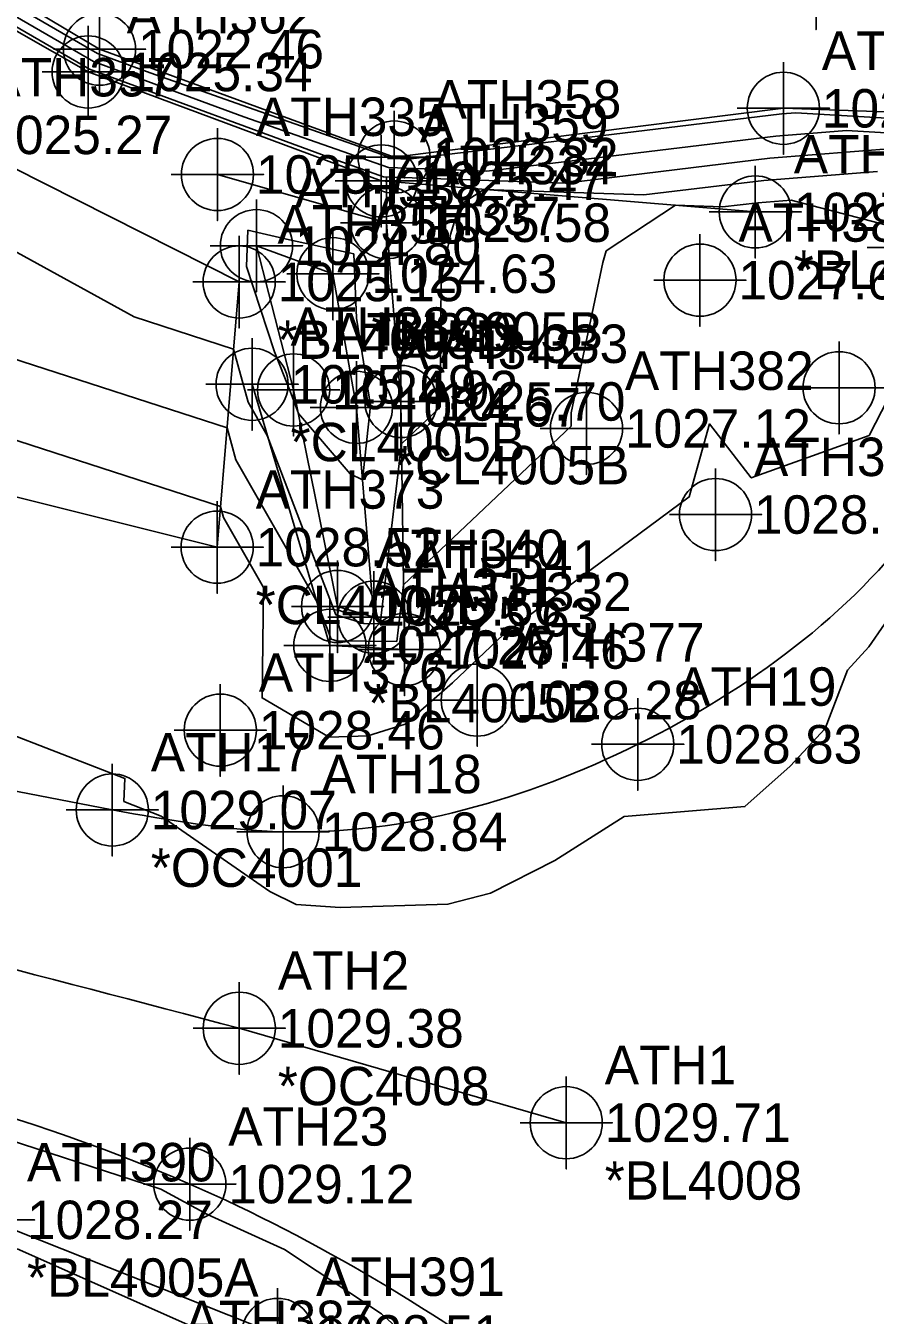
# Model space of a CAD drawing. Extents: x 1213164 to 1213550, y 766120 to 766870.
# Drawn here: x 1213249.2 to 1213304.4, y 766399.6 to 766483.4 of the extents above; entities that cross this region are included whole.
import ezdxf

# ---------------------------------------------------------------- set-up
doc = ezdxf.new("R2010")
doc.units = 0
for name, color, linetype in [('Default', 7, 'Continuous'), ('Exist DTM Breakline', 7, 'Continuous'), ('Exist DTM Breakline Cogo Comment', 7, 'Continuous'), ('Exist DTM Breakline Cogo Elevation', 7, 'Continuous'), ('Exist DTM Breakline Cogo Number', 7, 'Continuous'), ('Exist DTM Breakline Cogo Point CELL', 7, 'Continuous'), ('Exist DTM Crownline', 7, 'Continuous'), ('Exist DTM Crownline Cogo Point CELL', 7, 'Continuous'), ('Exist DTM Drainline Cogo Elevation', 7, 'Continuous'), ('Exist DTM Drainline Cogo Number', 7, 'Continuous'), ('Exist DTM Drainline Cogo Point CELL', 7, 'Continuous'), ('Exist DTM Regular Point CELL', 7, 'Continuous'), ('Exist DTM Regular Point Cogo Comment', 7, 'Continuous'), ('Exist DTM Regular Point Cogo Elevation', 7, 'Continuous'), ('Exist DTM Regular Point Cogo Number', 7, 'Continuous'), ('Exist DTM Regular Point Underwater CELL', 7, 'Continuous'), ('Exist DTM Regular Point Underwater Cogo Comment', 7, 'Continuous'), ('Exist DTM Regular Point Underwater Cogo Elevation', 7, 'Continuous'), ('Exist DTM Regular Point Underwater Cogo Number', 7, 'Continuous'), ('Exist Hydro Stream or Body of Water', 7, 'Continuous'), ('Exist Roads EOP', 7, 'Continuous'), ('Exist Roads EOP Cogo Point CELL', 7, 'Continuous')]:
    doc.layers.add(name, color=color, linetype=linetype)

msp = doc.modelspace()

# ---------------------------------------------------------------- linework, layer by layer
at = {"layer": 'Default'}
for points in [[(1213232.0588285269, 766494.9257890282), (1213249.4618614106, 766484.155977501), (1213253.8233532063, 766481.6289549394), (1213257.2612087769, 766480.3647865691), (1213273.0448975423, 766474.7949686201), (1213274.015282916, 766474.7610461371), (1213298.2993294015, 766477.708404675), (1213299.2070299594, 766477.7805484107), (1213310.3054437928, 766477.1165972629)], [(1213232.8561839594, 766492.4547874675), (1213253.311741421, 766480.6029584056), (1213269.4354109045, 766474.6739621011), (1213272.4180544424, 766473.6214336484), (1213284.2307344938, 766473.2084890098), (1213297.5165715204, 766474.8209931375), (1213305.7740741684, 766475.4772966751)], [(1213241.159022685, 766488.3053824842), (1213253.5675473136, 766481.1159566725), (1213263.3483098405, 766477.5193743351), (1213272.7314759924, 766474.2082011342), (1213279.123008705, 766473.9847675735), (1213297.907950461, 766476.2646989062), (1213302.490552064, 766476.6289225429), (1213309.1317715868, 766476.2316184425)], [(1213241.8495821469, 766472.4040495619), (1213256.20619088, 766464.510006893), (1213262.6712030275, 766462.4170151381), (1213263.6274647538, 766458.9801034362), (1213264.86498659, 766456.8053627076), (1213269.324798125, 766445.152285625), (1213271.1324427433, 766444.5771108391), (1213272.1914347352, 766444.5668498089), (1213273.5869493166, 766456.2710233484), (1213276.0928715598, 766458.6461009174), (1213276.1688284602, 766466.9726738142), (1213276.7759325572, 766469.8664609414), (1213277.3577727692, 766471.7631941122), (1213278.9261876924, 766472.7962), (1213289.338460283, 766472.4322104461), (1213297.1251925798, 766473.3772873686), (1213304.5200093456, 766473.965024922)], [(1213248.2040699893, 766461.848819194), (1213262.2482288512, 766457.3021442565), (1213262.8244183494, 766455.2312546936), (1213268.0929559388, 766445.9726679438), (1213269.010423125, 766443.575410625), (1213269.3822896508, 766443.4570863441), (1213273.2728110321, 766443.4193894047), (1213273.7105256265, 766447.0904994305), (1213284.5974587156, 766457.40898024), (1213284.6054756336, 766458.2878135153), (1213286.6546322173, 766468.0552042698), (1213286.8816918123, 766468.7953928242), (1213291.3872133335, 766471.7628666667), (1213294.4461860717, 766471.6559318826), (1213296.7338136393, 766471.9335815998), (1213298.9063021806, 766472.1062502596), (1213306.933585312, 766469.9994549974)], [(1213270.4933911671, 766468.6119369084), (1213266.3054523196, 766469.5157680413), (1213263.606791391, 766470.1433090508), (1213263.5131686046, 766467.7872063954), (1213265.3257180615, 766462.2346563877), (1213266.2945692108, 766459.7992923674), (1213266.883391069, 766458.2377523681), (1213270.2464119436, 766454.3210323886), (1213271.0436659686, 766453.933051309), (1213271.578352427, 766458.7532951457), (1213270.661723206, 766464.4384603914), (1213270.4933911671, 766468.6119369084)], [(1213240.2019490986, 766459.1876314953), (1213261.825254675, 766452.1872733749), (1213262.021371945, 766451.4824059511), (1213264.6126897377, 766446.9285918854), (1213264.522, 766439.7541904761), (1213268.8770723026, 766437.2006966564), (1213271.399363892, 766437.2813272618), (1213273.82585679, 766438.0367576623), (1213276.8905679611, 766440.7315667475), (1213280.2210275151, 766443.8767730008), (1213292.27047881, 766452.8124391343), (1213293.5964207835, 766457.5562385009), (1213296.3081834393, 766454.0494878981), (1213303.9691910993, 766456.8052290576), (1213305.1746980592, 766459.1640712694)], [(1213243.076208, 766439.375128), (1213255.6098, 766434.52024), (1213255.5513245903, 766433.0317836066), (1213257.9766434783, 766432.0649565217), (1213260.6527552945, 766430.2095082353), (1213265.025962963, 766427.1774000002), (1213266.734679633, 766426.3176169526), (1213269.5934405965, 766426.1347008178), (1213276.5976029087, 766426.3405219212), (1213279.3752267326, 766427.0700548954), (1213283.544682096, 766429.1848296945), (1213288.047086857, 766432.045632), (1213295.896795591, 766432.6861543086), (1213298.8266954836, 766435.3265397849), (1213301.119690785, 766437.7595055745), (1213302.5606152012, 766441.5653675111), (1213303.9465482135, 766443.0621877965), (1213305.9890845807, 766446.0090692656)], [(1213230.27052591, 766397.0919027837), (1213210.0502904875, 766409.2118387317), (1213208.8059889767, 766410.1645017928), (1213208.711069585, 766410.2255837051), (1213204.8157449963, 766413.1740985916), (1213199.0997527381, 766413.9635790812), (1213198.2274566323, 766414.1920961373), (1213195.841164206, 766414.7708472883), (1213188.354160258, 766420.7673471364), (1213197.3822142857, 766420.732), (1213197.7500768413, 766420.6560518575), (1213202.4220598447, 766420.4321571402), (1213209.9590629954, 766419.4594779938), (1213216.0055279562, 766418.2743214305), (1213223.5451874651, 766417.0549871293), (1213231.5942266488, 766415.6015483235), (1213231.834396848, 766415.5269702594), (1213244.5309932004, 766412.4389489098), (1213246.2129118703, 766411.6392958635), (1213257.9370376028, 766407.8232432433), (1213260.9764697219, 766406.1926104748), (1213265.9803135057, 766403.9173045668), (1213272.2724532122, 766399.7307453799), (1213280.2315516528, 766392.5875649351)], [(1213248.618107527, 766403.962344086), (1213263.0023333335, 766397.5598888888)]]:
    msp.add_lwpolyline(points, dxfattribs=at)
at = {"layer": 'Exist DTM Breakline'}
for points in [[(1213296.571, 766471.333), (1213272.272, 766473.348), (1213253.224, 766480.427), (1213224.639, 766496.741)], [(1213263.0320000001, 766466.78), (1213244.11, 766476.337), (1213210.348, 766487.596), (1213206.1230000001, 766467.821), (1213232.848, 766456.742), (1213261.607, 766449.5480000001), (1213263.0320000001, 766466.78)], [(1213268.929, 766443.167), (1213273.767, 766442.895), (1213273.55, 766459.0160000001), (1213272.617, 766470.6290000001), (1213261.6230000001, 766473.765)], [(1213269.129, 766467.316), (1213264.158, 766469.137), (1213266.574, 766459.761), (1213269.432, 766445.6900000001), (1213271.787, 766444.996), (1213270.653, 766458.63), (1213269.129, 766467.316)], [(1213263.874, 766460.131), (1213268.929, 766443.167)], [(1213246.745, 766405.836), (1213265.533, 766398.3910000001), (1213284.1840000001, 766386.845), (1213308.1400000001, 766364.949), (1213319.74, 766349.721)]]:
    msp.add_lwpolyline(points, dxfattribs=at)
at = {"layer": 'Exist DTM Breakline Cogo Point CELL'}
for points in [[(1213253.224, 766483.427), (1213253.224, 766477.427), (1213253.224, 766480.427), (1213256.224, 766480.427), (1213250.224, 766480.427)], [(1213261.6230000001, 766476.765), (1213261.6230000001, 766470.765), (1213261.6230000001, 766473.765), (1213264.6230000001, 766473.765), (1213258.6230000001, 766473.765)], [(1213272.272, 766476.348), (1213272.272, 766470.348), (1213272.272, 766473.348), (1213275.272, 766473.348), (1213269.272, 766473.348)], [(1213296.571, 766474.333), (1213296.571, 766468.333), (1213296.571, 766471.333), (1213299.571, 766471.333), (1213293.571, 766471.333)], [(1213272.617, 766473.6290000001), (1213272.617, 766467.6290000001), (1213272.617, 766470.6290000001), (1213275.617, 766470.6290000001), (1213269.617, 766470.6290000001)], [(1213264.158, 766472.137), (1213264.158, 766466.137), (1213264.158, 766469.137), (1213267.158, 766469.137), (1213261.158, 766469.137)], [(1213263.0320000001, 766469.78), (1213263.0320000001, 766463.78), (1213263.0320000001, 766466.78), (1213266.0320000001, 766466.78), (1213260.0320000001, 766466.78)], [(1213269.129, 766470.316), (1213269.129, 766464.316), (1213269.129, 766467.316), (1213272.129, 766467.316), (1213266.129, 766467.316)], [(1213263.874, 766463.131), (1213263.874, 766457.131), (1213263.874, 766460.131), (1213266.874, 766460.131), (1213260.874, 766460.131)], [(1213266.574, 766462.761), (1213266.574, 766456.761), (1213266.574, 766459.761), (1213269.574, 766459.761), (1213263.574, 766459.761)], [(1213270.653, 766461.63), (1213270.653, 766455.63), (1213270.653, 766458.63), (1213273.653, 766458.63), (1213267.653, 766458.63)], [(1213273.55, 766462.0160000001), (1213273.55, 766456.0160000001), (1213273.55, 766459.0160000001), (1213276.55, 766459.0160000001), (1213270.55, 766459.0160000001)], [(1213261.607, 766452.5480000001), (1213261.607, 766446.5480000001), (1213261.607, 766449.5480000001), (1213264.607, 766449.5480000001), (1213258.607, 766449.5480000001)], [(1213269.432, 766448.6900000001), (1213269.432, 766442.6900000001), (1213269.432, 766445.6900000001), (1213272.432, 766445.6900000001), (1213266.432, 766445.6900000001)], [(1213271.787, 766447.996), (1213271.787, 766441.996), (1213271.787, 766444.996), (1213274.787, 766444.996), (1213268.787, 766444.996)], [(1213268.929, 766446.167), (1213268.929, 766440.167), (1213268.929, 766443.167), (1213271.929, 766443.167), (1213265.929, 766443.167)], [(1213273.767, 766445.895), (1213273.767, 766439.895), (1213273.767, 766442.895), (1213276.767, 766442.895), (1213270.767, 766442.895)], [(1213246.745, 766408.836), (1213246.745, 766402.836), (1213246.745, 766405.836), (1213249.745, 766405.836), (1213243.745, 766405.836)], [(1213265.533, 766401.3910000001), (1213265.533, 766395.3910000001), (1213265.533, 766398.3910000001), (1213268.533, 766398.3910000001), (1213262.533, 766398.3910000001)]]:
    msp.add_lwpolyline(points, dxfattribs=at)
for centre in [(1213253.224, 766480.427), (1213261.6230000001, 766473.765), (1213272.272, 766473.348), (1213296.571, 766471.333), (1213272.617, 766470.6290000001), (1213264.158, 766469.137), (1213263.0320000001, 766466.78), (1213269.129, 766467.316), (1213263.874, 766460.131), (1213266.574, 766459.761), (1213273.55, 766459.0160000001), (1213270.653, 766458.63), (1213261.607, 766449.5480000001), (1213269.432, 766445.6900000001), (1213271.787, 766444.996), (1213268.929, 766443.167), (1213273.767, 766442.895), (1213265.533, 766398.3910000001)]:
    msp.add_circle(centre, 2.344041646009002, dxfattribs=at)
at = {"layer": 'Exist DTM Crownline'}
msp.add_line((1213284.287, 766412.148), (1213263.045, 766418.285), dxfattribs=at)
msp.add_spline([(1213263.045, 766418.285), (1213224.299, 766428.074), (1213217.9282366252, 766429.4550394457), (1213211.4867235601, 766430.48415642), (1213204.999098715, 766431.2859451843), (1213198.49, 766431.985), (1213182.9002335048, 766433.2004959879), (1213167.31, 766433.447), (1213167.31, 766433.4469999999)], degree=3, dxfattribs=at)
at = {"layer": 'Exist DTM Crownline Cogo Point CELL'}
for points in [[(1213263.045, 766421.285), (1213263.045, 766415.285), (1213263.045, 766418.285), (1213266.045, 766418.285), (1213260.045, 766418.285)], [(1213284.287, 766415.148), (1213284.287, 766409.148), (1213284.287, 766412.148), (1213287.287, 766412.148), (1213281.287, 766412.148)]]:
    msp.add_lwpolyline(points, dxfattribs=at)
for centre in [(1213263.045, 766418.285), (1213284.287, 766412.148)]:
    msp.add_circle(centre, 2.344041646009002, dxfattribs=at)
at = {"layer": 'Exist DTM Drainline Cogo Point CELL'}
for points in [[(1213253.962, 766484.907), (1213253.962, 766478.907), (1213253.962, 766481.907), (1213256.962, 766481.907), (1213250.962, 766481.907)], [(1213298.396, 766481.0650000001), (1213298.396, 766475.0650000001), (1213298.396, 766478.0650000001), (1213301.396, 766478.0650000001), (1213295.396, 766478.0650000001)], [(1213273.101, 766477.9), (1213273.101, 766471.9), (1213273.101, 766474.9), (1213276.101, 766474.9), (1213270.101, 766474.9)]]:
    msp.add_lwpolyline(points, dxfattribs=at)
for centre in [(1213253.962, 766481.907), (1213298.396, 766478.0650000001), (1213273.101, 766474.9)]:
    msp.add_circle(centre, 2.344041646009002, dxfattribs=at)
at = {"layer": 'Exist DTM Regular Point CELL'}
for points in [[(1213306.844, 766472.02), (1213306.844, 766466.02), (1213306.844, 766469.02), (1213309.844, 766469.02), (1213303.844, 766469.02)], [(1213292.977, 766469.8960000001), (1213292.977, 766463.8960000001), (1213292.977, 766466.8960000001), (1213295.977, 766466.8960000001), (1213289.977, 766466.8960000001)], [(1213302.014, 766462.906), (1213302.014, 766456.906), (1213302.014, 766459.906), (1213305.014, 766459.906), (1213299.014, 766459.906)], [(1213285.601, 766460.263), (1213285.601, 766454.263), (1213285.601, 766457.263), (1213288.601, 766457.263), (1213282.601, 766457.263)], [(1213293.987, 766454.667), (1213293.987, 766448.667), (1213293.987, 766451.667), (1213296.987, 766451.667), (1213290.987, 766451.667)], [(1213278.507, 766442.612), (1213278.507, 766436.612), (1213278.507, 766439.612), (1213281.507, 766439.612), (1213275.507, 766439.612)], [(1213261.81, 766440.654), (1213261.81, 766434.654), (1213261.81, 766437.654), (1213264.81, 766437.654), (1213258.81, 766437.654)]]:
    msp.add_lwpolyline(points, dxfattribs=at)
for centre in [(1213292.977, 766466.8960000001), (1213302.014, 766459.906), (1213285.601, 766457.263), (1213293.987, 766451.667), (1213278.507, 766439.612), (1213261.81, 766437.654)]:
    msp.add_circle(centre, 2.344041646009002, dxfattribs=at)
at = {"layer": 'Exist DTM Regular Point Underwater CELL'}
msp.add_lwpolyline([(1213300.523, 766489.1780000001), (1213300.523, 766483.1780000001), (1213300.523, 766486.1780000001), (1213303.523, 766486.1780000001), (1213297.523, 766486.1780000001)], dxfattribs=at)
at = {"layer": 'Exist Hydro Stream or Body of Water'}
for points in [[(1213298.396, 766478.0650000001), (1213273.101, 766474.9), (1213253.962, 766481.907), (1213225.147, 766499.034)], [(1213342.815, 766469.469), (1213342.1130000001, 766469.463), (1213336.847, 766471.476), (1213315.962, 766476.373), (1213310.985, 766477.6290000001), (1213298.396, 766478.0650000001)]]:
    msp.add_lwpolyline(points, dxfattribs=at)
at = {"layer": 'Exist Roads EOP'}
msp.add_line((1213226.176, 766438.046), (1213254.7920000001, 766432.471), dxfattribs=at)
for points in [[(1213254.7920000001, 766432.471), (1213265.8900000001, 766431.056), (1213288.9340000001, 766436.7390000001), (1213307.368, 766451.415), (1213314.463, 766464.218)], [(1213169.012, 766424.202), (1213197.361, 766422.679), (1213222.732, 766418.674), (1213259.828, 766408.159), (1213283.389, 766394.331), (1213303.908, 766375.84), (1213322.371, 766351.308)]]:
    msp.add_spline(points, degree=3, dxfattribs=at)
at = {"layer": 'Exist Roads EOP Cogo Point CELL'}
for points in [[(1213288.9340000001, 766439.7390000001), (1213288.9340000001, 766433.7390000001), (1213288.9340000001, 766436.7390000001), (1213291.9340000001, 766436.7390000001), (1213285.9340000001, 766436.7390000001)], [(1213254.7920000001, 766435.471), (1213254.7920000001, 766429.471), (1213254.7920000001, 766432.471), (1213257.7920000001, 766432.471), (1213251.7920000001, 766432.471)], [(1213265.8900000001, 766434.056), (1213265.8900000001, 766428.056), (1213265.8900000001, 766431.056), (1213268.8900000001, 766431.056), (1213262.8900000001, 766431.056)], [(1213259.828, 766411.159), (1213259.828, 766405.159), (1213259.828, 766408.159), (1213262.828, 766408.159), (1213256.828, 766408.159)]]:
    msp.add_lwpolyline(points, dxfattribs=at)
for centre in [(1213288.9340000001, 766436.7390000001), (1213254.7920000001, 766432.471), (1213265.8900000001, 766431.056), (1213259.828, 766408.159)]:
    msp.add_circle(centre, 2.344041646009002, dxfattribs=at)

# ---------------------------------------------------------------- texts
at = {"layer": 'Exist DTM Breakline Cogo Comment'}
for s, p in [('*BL4005C', (1213299.071, 766466.333)), ('*BL4005B', (1213271.629, 766462.316)), ('*BL4005D', (1213265.5320000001, 766461.78)), ('*CL4005B', (1213266.374, 766455.131)), ('*CL4005B', (1213273.153, 766453.63)), ('*CL4005D', (1213264.107, 766444.5480000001)), ('*BL4005B', (1213271.429, 766438.167)), ('*BL4005A', (1213249.245, 766400.836))]:
    msp.add_text(s, height=2.5, dxfattribs=at).set_placement(p)
at = {"layer": 'Exist DTM Breakline Cogo Elevation'}
for s, p in [('1025.34', (1213255.724, 766479.177)), ('1025.27', (1213246.61, 766475.087)), ('1025.71', (1213264.1230000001, 766472.515)), ('1025.47', (1213274.772, 766472.098)), ('1027.42', (1213299.071, 766470.083)), ('1025.58', (1213275.117, 766469.3790000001)), ('1024.80', (1213266.658, 766467.887)), ('1025.15', (1213265.5320000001, 766465.53)), ('1024.63', (1213271.629, 766466.066)), ('1025.69', (1213266.374, 766458.881)), ('1024.92', (1213269.074, 766458.511)), ('1024.67', (1213273.153, 766457.38)), ('1025.70', (1213276.05, 766457.7660000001)), ('1028.52', (1213264.107, 766448.2980000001)), ('1025.66', (1213271.932, 766444.4400000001)), ('1025.63', (1213274.287, 766443.746)), ('1027.26', (1213271.429, 766441.917)), ('1027.46', (1213276.267, 766441.645)), ('1028.27', (1213249.245, 766404.586)), ('1028.51', (1213268.033, 766397.1410000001))]:
    msp.add_text(s, height=2.5, dxfattribs=at).set_placement(p)
at = {"layer": 'Exist DTM Breakline Cogo Number'}
for s, p in [('ATH362', (1213255.724, 766482.927)), ('ATH357', (1213246.61, 766478.837)), ('ATH335', (1213264.1230000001, 766476.265)), ('ATH359', (1213274.772, 766475.848)), ('ATH334', (1213275.117, 766473.1290000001)), ('ATH351', (1213299.071, 766473.833)), ('ATH338', (1213266.658, 766471.637)), ('ATH337', (1213271.629, 766469.816)), ('ATH355', (1213265.5320000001, 766469.28)), ('ATH336', (1213266.374, 766462.631)), ('ATH339', (1213269.074, 766462.261)), ('ATH333', (1213276.05, 766461.5160000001)), ('ATH342', (1213273.153, 766461.13)), ('ATH373', (1213264.107, 766452.0480000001)), ('ATH340', (1213271.932, 766448.1900000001)), ('ATH341', (1213274.287, 766447.496)), ('ATH331', (1213271.429, 766445.667)), ('ATH332', (1213276.267, 766445.395)), ('ATH390', (1213249.245, 766408.336)), ('ATH391', (1213268.033, 766400.8910000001)), ('ATH387', (1213259.492, 766398.086))]:
    msp.add_text(s, height=2.5, dxfattribs=at).set_placement(p)
at = {"layer": 'Exist DTM Drainline Cogo Elevation'}
for s, p in [('1022.46', (1213256.462, 766480.657)), ('1022.75', (1213300.896, 766476.8150000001)), ('1022.82', (1213275.601, 766473.65))]:
    msp.add_text(s, height=2.5, dxfattribs=at).set_placement(p)
at = {"layer": 'Exist DTM Drainline Cogo Number'}
for s, p in [('ATH350', (1213300.896, 766480.5650000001)), ('ATH358', (1213275.601, 766477.4))]:
    msp.add_text(s, height=2.5, dxfattribs=at).set_placement(p)
at = {"layer": 'Exist DTM Regular Point Cogo Comment'}
msp.add_text('*OC4001', height=2.5, dxfattribs=at).set_placement((1213257.2920000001, 766427.471))
at = {"layer": 'Exist DTM Regular Point Cogo Elevation'}
for s, p in [('1027.64', (1213295.477, 766465.6460000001)), ('1027.12', (1213288.101, 766456.013)), ('1028.23', (1213296.487, 766450.417)), ('1028.28', (1213281.007, 766438.362)), ('1028.46', (1213264.31, 766436.404)), ('1028.83', (1213291.4340000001, 766435.4890000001)), ('1029.07', (1213257.2920000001, 766431.221)), ('1028.84', (1213268.3900000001, 766429.806)), ('1029.12', (1213262.328, 766406.909))]:
    msp.add_text(s, height=2.5, dxfattribs=at).set_placement(p)
at = {"layer": 'Exist DTM Regular Point Cogo Number'}
for s, p in [('ATH381', (1213295.477, 766469.3960000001)), ('ATH382', (1213288.101, 766459.763)), ('ATH378', (1213296.487, 766454.167)), ('ATH377', (1213281.007, 766442.112)), ('ATH376', (1213264.31, 766440.154)), ('ATH19', (1213291.4340000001, 766439.2390000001)), ('ATH17', (1213257.2920000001, 766434.971)), ('ATH18', (1213268.3900000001, 766433.556)), ('ATH23', (1213262.328, 766410.659))]:
    msp.add_text(s, height=2.5, dxfattribs=at).set_placement(p)
at = {"layer": 'Exist DTM Regular Point Underwater Cogo Comment'}
for s, p in [('*OC4008', (1213265.545, 766413.285)), ('*BL4008', (1213286.787, 766407.148))]:
    msp.add_text(s, height=2.5, dxfattribs=at).set_placement(p)
at = {"layer": 'Exist DTM Regular Point Underwater Cogo Elevation'}
for s, p in [('1029.38', (1213265.545, 766417.035)), ('1029.71', (1213286.787, 766410.898))]:
    msp.add_text(s, height=2.5, dxfattribs=at).set_placement(p)
at = {"layer": 'Exist DTM Regular Point Underwater Cogo Number'}
for s, p in [('ATH2', (1213265.545, 766420.785)), ('ATH1', (1213286.787, 766414.648))]:
    msp.add_text(s, height=2.5, dxfattribs=at).set_placement(p)

doc.saveas('drawing.dxf')
